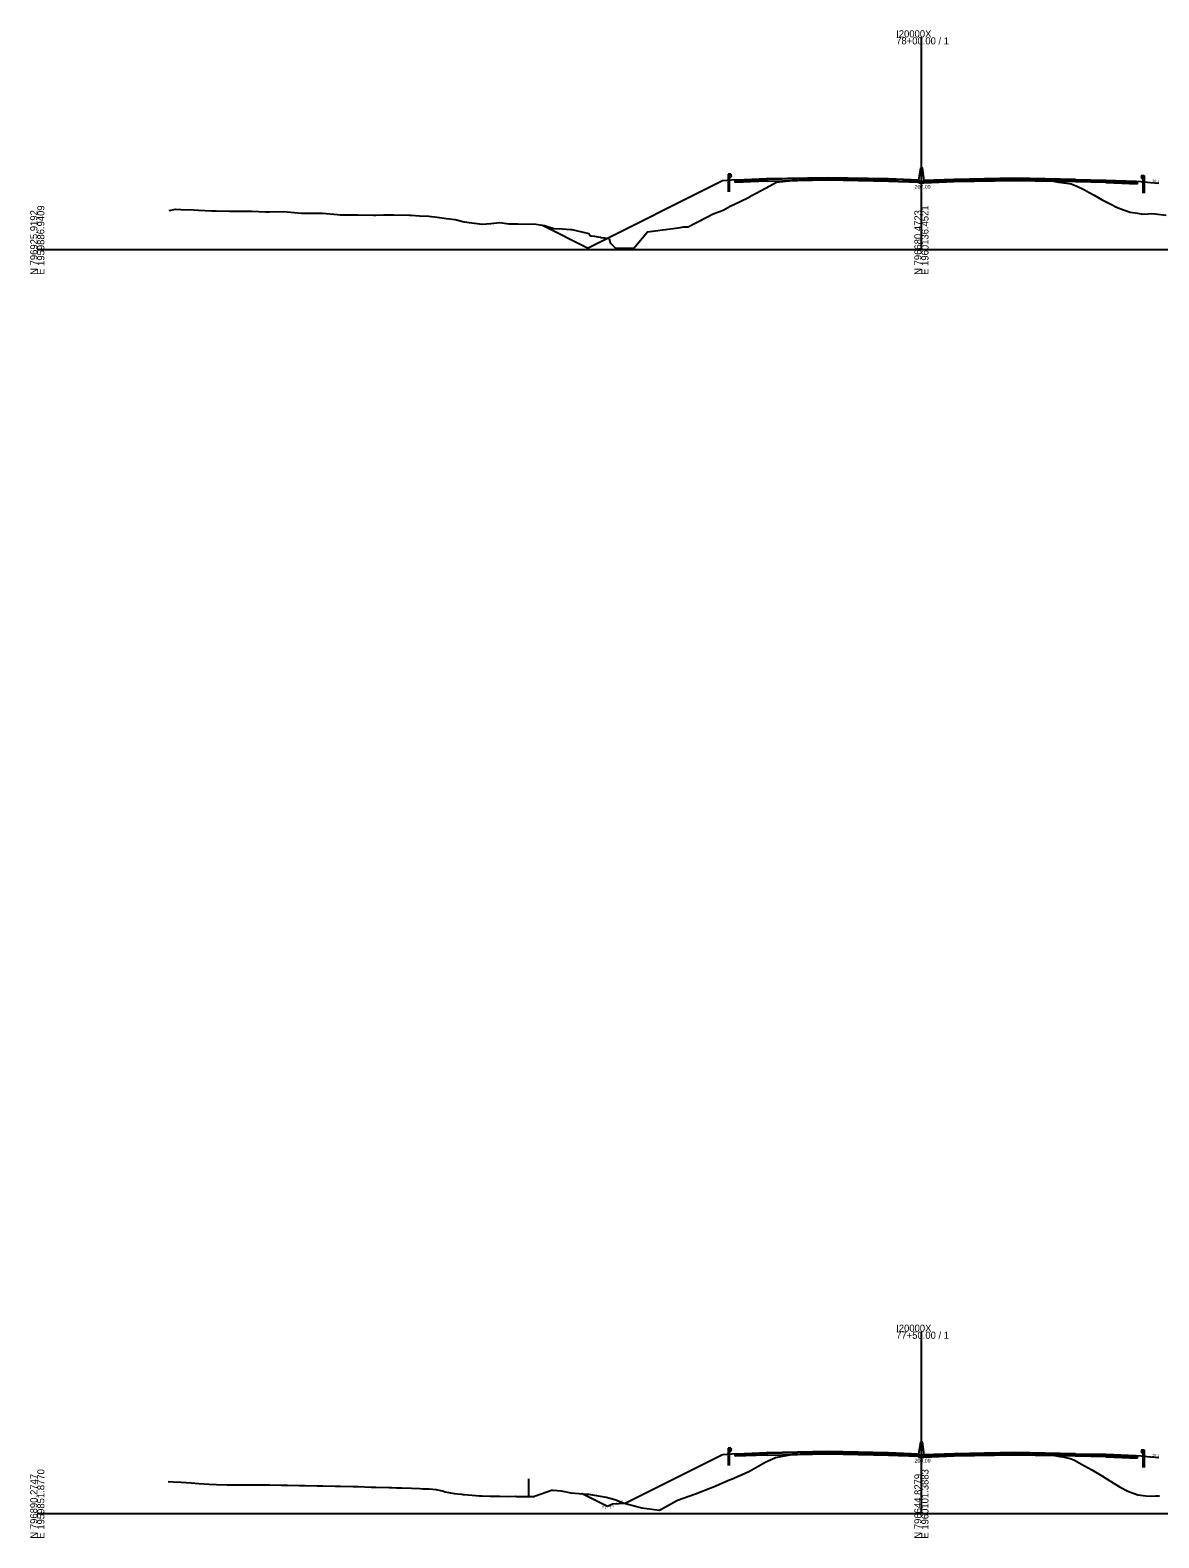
# Model space of a CAD drawing. Extents: x -4026 to 9638, y -10 to 19609.
# Drawn here: x -1003 to -556, y 7490 to 8087 of the extents above; entities that cross this region are included whole.
import ezdxf

# ---------------------------------------------------------------- set-up
doc = ezdxf.new("R2010")
doc.units = 0
for name, color, linetype in [('Default', 7, 'Continuous'), ('RD_EX_Fence_Other', 7, 'Continuous'), ('RD_GPK_XS_Cell', 7, 'Continuous'), ('RD_XS_Base', 7, 'Continuous'), ('RD_XS_ExGround', 7, 'Continuous'), ('RD_XS_GR', 7, 'Continuous'), ('RD_XS_Greenside', 7, 'Continuous'), ('RD_XS_MedBWall', 7, 'Continuous'), ('RD_XS_Pave', 7, 'Continuous'), ('RD_XS_PaveOvlay', 7, 'Continuous'), ('RD_XS_TX_Ditch', 7, 'Continuous'), ('RD_XS_TX_Elev_EX', 7, 'Continuous'), ('RD_XS_TX_Slope', 7, 'Continuous')]:
    doc.layers.add(name, color=color, linetype=linetype)

msp = doc.modelspace()

# ---------------------------------------------------------------- linework, layer by layer
at = {"layer": 'RD_EX_Fence_Other'}
msp.add_line((-805.49, 7513.7), (-805.49, 7506.7), dxfattribs=at)
at = {"layer": 'RD_GPK_XS_Cell'}
for p, q in [((-650, 8000), (-650, 8083.98)), ((-1000, 8000), (-650, 8000)), ((-650, 8000), (-300, 8000)), ((-650, 7500), (-650, 7571.86)), ((-1000, 7500), (-650, 7500)), ((-650, 7500), (-300, 7500))]:
    msp.add_line(p, q, dxfattribs=at)
at = {"layer": 'RD_XS_Base'}
for points in [[(-723.75, 8027.26), (-723.25, 8027.28), (-711.25, 8027.75)], [(-723.75, 8026.59), (-723.75, 8027.26)], [(-711.25, 8027.08), (-723.75, 8026.59)], [(-711.25, 8027.75), (-711, 8027.75)], [(-711.25, 8027.08), (-711.25, 8027.75)], [(-711, 8027.08), (-711.25, 8027.08)], [(-663, 8027.76), (-687, 8028.24), (-711, 8027.75)], [(-711, 8027.75), (-711, 8027.08)], [(-711, 8027.08), (-687, 8027.57), (-663, 8027.09)], [(-651, 8027.29), (-663, 8027.76)], [(-663, 8027.76), (-663, 8027.09)], [(-663, 8027.09), (-651, 8026.62)], [(-651, 8026.62), (-651, 8027.29)], [(-649, 8026.94), (-637, 8027.43)], [(-649, 8026.27), (-649, 8026.94)], [(-637, 8026.76), (-649, 8026.27)], [(-637, 8027.43), (-613, 8027.92), (-589, 8027.43)], [(-637, 8026.76), (-637, 8027.43)], [(-589, 8026.76), (-613, 8027.25), (-637, 8026.76)], [(-589, 8027.43), (-577, 8027.19)], [(-589, 8026.76), (-589, 8027.43)], [(-577, 8026.52), (-589, 8026.76)], [(-577, 8027.19), (-577, 8026.52)], [(-564.5, 8026.7), (-565, 8026.72), (-577, 8027.19)], [(-577, 8026.52), (-564.5, 8026.03)], [(-564.5, 8026.03), (-564.5, 8026.7)], [(-723.75, 7523.23), (-723.25, 7523.25), (-711.25, 7523.72)], [(-723.75, 7522.56), (-723.75, 7523.23)], [(-711.25, 7523.05), (-723.75, 7522.56)], [(-711.25, 7523.72), (-711, 7523.73)], [(-711.25, 7523.05), (-711.25, 7523.72)], [(-711, 7523.06), (-711.25, 7523.05)], [(-663, 7523.73), (-687, 7524.22), (-711, 7523.73)], [(-711, 7523.73), (-711, 7523.06)], [(-711, 7523.06), (-687, 7523.55), (-663, 7523.06)], [(-651, 7523.26), (-663, 7523.73)], [(-663, 7523.73), (-663, 7523.06)], [(-663, 7523.06), (-651, 7522.59)], [(-651, 7522.59), (-651, 7523.26)], [(-649, 7522.76), (-637, 7523.25)], [(-649, 7522.09), (-649, 7522.76)], [(-637, 7522.58), (-649, 7522.09)], [(-637, 7523.25), (-613, 7523.73), (-589, 7523.25)], [(-637, 7522.58), (-637, 7523.25)], [(-589, 7522.58), (-613, 7523.06), (-637, 7522.58)], [(-589, 7523.25), (-577, 7523.01)], [(-589, 7522.58), (-589, 7523.25)], [(-577, 7522.34), (-589, 7522.58)], [(-577, 7523.01), (-577, 7522.34)], [(-564.5, 7522.51), (-565, 7522.53), (-577, 7523.01)], [(-577, 7522.34), (-564.5, 7521.84)], [(-564.5, 7521.84), (-564.5, 7522.51)]]:
    msp.add_lwpolyline(points, dxfattribs=at)
at = {"layer": 'RD_XS_ExGround'}
for points in [[(-947.76, 8015.45), (-945.29, 8015.93), (-943.18, 8015.87), (-938.16, 8015.69), (-936.16, 8015.54), (-931.03, 8015.37), (-929.15, 8015.27), (-923.9, 8015.16), (-922.14, 8015.22), (-916.77, 8015.19), (-915.12, 8015.21), (-909.64, 8014.92), (-908.11, 8014.96), (-902.51, 8015.04), (-901.09, 8014.94), (-898.26, 8014.65), (-895.38, 8014.46), (-894.72, 8014.47), (-894.08, 8014.41), (-891.19, 8014.35), (-888.25, 8014.41), (-887.65, 8014.44), (-887.07, 8014.39), (-881.12, 8013.83), (-880.05, 8013.79), (-873.99, 8013.75), (-873.51, 8013.75), (-873.04, 8013.75), (-866.86, 8013.65), (-866.44, 8013.64), (-866.03, 8013.66), (-862.9, 8013.8), (-859.73, 8013.73), (-859.37, 8013.71), (-859.01, 8013.75), (-852.6, 8013.63), (-852, 8013.62), (-848.76, 8013.42), (-844.98, 8013.23), (-841.69, 8012.88), (-837.97, 8012.32), (-834.62, 8011.85), (-830.96, 8011), (-823.94, 8010.03), (-820.47, 8010.36), (-816.93, 8010.73), (-813.4, 8010.17), (-809.82, 8010.24), (-802.69, 8010.04), (-799.26, 8009.5), (-795.56, 8008.37), (-792.19, 8008.26), (-788.87, 8007.94), (-788.43, 8007.9), (-781.66, 8006.32), (-781.17, 8005.53), (-780.8, 8005.47), (-779.41, 8005.25), (-778.09, 8005.04), (-777.1, 8004.88), (-776.78, 8004.83), (-775.78, 8004.67), (-775.45, 8004.62), (-774.74, 8004.5), (-773.64, 8004.33), (-773.25, 8002.61), (-771.65, 8001.05), (-771.11, 8000.52), (-765.64, 8000.58), (-765.13, 8000.59), (-764.79, 8000.6), (-763.89, 8000.62), (-763.14, 8001.31), (-758.48, 8007.03), (-746.26, 8008.57), (-744.01, 8009.06), (-742.69, 8008.99), (-742.36, 8008.98), (-739.78, 8010.35), (-738.52, 8011.03), (-732.76, 8014.01), (-732.08, 8014.29), (-731.39, 8014.58), (-728.55, 8015.57), (-725.75, 8017.14), (-724.26, 8017.89), (-721.48, 8019.17), (-718.74, 8020.52), (-717.94, 8020.93), (-717.13, 8021.38), (-711.72, 8024.27), (-710, 8025.16), (-707.33, 8026.61), (-702.33, 8027.21), (-701.17, 8027.36), (-695.89, 8027.58), (-691.66, 8027.76), (-681.82, 8027.96), (-680.48, 8027.99), (-679.2, 8027.97), (-669.05, 8027.81), (-657.33, 8027.55), (-651.75, 8027.07), (-651.05, 8027.08), (-650, 8027.09), (-647.77, 8027.1), (-644.4, 8027.32), (-642.43, 8027.46), (-636.64, 8027.58), (-630.82, 8027.71), (-624.59, 8027.84), (-619.17, 8027.95), (-615.91, 8027.87), (-607.64, 8027.65), (-600.03, 8027.27), (-598.85, 8027.22), (-598.43, 8027.15), (-595.78, 8026.74), (-594.48, 8026.52), (-590.66, 8026.03), (-588.79, 8025.29), (-585.48, 8023.59), (-583.59, 8022.58), (-581.66, 8021.56), (-580.05, 8020.67), (-578.46, 8019.69), (-574.53, 8017.68), (-572.98, 8016.86), (-571.45, 8016.21), (-567.4, 8014.83), (-564.44, 8014.36), (-562.37, 8013.95), (-560.27, 8014.18), (-558.84, 8014.27), (-557.42, 8014.21), (-553.14, 8013.61)], [(-948.17, 7512.61), (-946.21, 7512.5), (-943.09, 7512.29), (-939.08, 7512.01), (-936.07, 7511.8), (-931.95, 7511.53), (-929.06, 7511.45), (-924.82, 7511.31), (-922.05, 7511.28), (-917.69, 7511.27), (-915.03, 7511.25), (-910.56, 7511.25), (-908.02, 7511.25), (-903.43, 7511.17), (-901, 7511.14), (-896.3, 7511.07), (-893.99, 7511.05), (-889.17, 7510.94), (-886.98, 7510.88), (-882.04, 7510.78), (-879.96, 7510.75), (-874.91, 7510.64), (-872.95, 7510.57), (-867.78, 7510.42), (-865.94, 7510.38), (-860.65, 7510.23), (-859.78, 7510.22), (-857.87, 7510.15), (-857.18, 7510.13), (-855.66, 7510.06), (-851.86, 7509.92), (-848.6, 7509.8), (-847.42, 7509.76), (-846.91, 7509.74), (-845.64, 7509.68), (-844.89, 7509.66), (-842.1, 7509.49), (-839.26, 7508.71), (-838.56, 7508.55), (-837.88, 7508.37), (-835.03, 7507.86), (-832.13, 7507.59), (-831.49, 7507.51), (-830.87, 7507.46), (-825, 7506.95), (-824.42, 7506.93), (-823.85, 7506.94), (-820.89, 7506.83), (-817.87, 7506.79), (-817.35, 7506.79), (-816.84, 7506.77), (-813.81, 7506.6), (-810.74, 7506.74), (-810.28, 7506.69), (-809.83, 7506.7), (-803.61, 7506.7), (-803.21, 7506.7), (-802.81, 7506.99), (-796.48, 7509.14), (-796.14, 7509.17), (-795.8, 7509.15), (-792.6, 7508.85), (-788.78, 7508.18), (-782.22, 7507.58), (-781.77, 7507.54), (-774.76, 7506.38), (-771.39, 7505.48), (-767.74, 7504.03), (-760.73, 7502.2), (-754.73, 7501.39), (-753.7, 7501.26), (-746.57, 7505.22), (-739.44, 7507.67), (-732.68, 7510.36), (-732.31, 7510.49), (-725.66, 7513.33), (-725.18, 7513.54), (-718.65, 7516.42), (-718.05, 7516.73), (-711.63, 7520.35), (-710.92, 7520.7), (-707.74, 7522.16), (-702.02, 7523.12), (-700.93, 7523.31), (-695.28, 7523.55), (-691.79, 7523.69), (-685.05, 7523.85), (-680.44, 7523.95), (-674.26, 7523.84), (-668.93, 7523.74), (-662.76, 7523.61), (-657.45, 7523.5), (-652.62, 7523.14), (-651.92, 7523.08), (-650, 7523.09), (-648.54, 7523.1), (-647.93, 7523.1), (-646.18, 7523.22), (-642.39, 7523.48), (-640.89, 7523.51), (-630.84, 7523.73), (-623.21, 7523.86), (-619.26, 7523.94), (-614.53, 7523.81), (-607.69, 7523.64), (-600.33, 7523.3), (-598.77, 7523.21), (-597.95, 7523.06), (-595.22, 7522.55), (-594.04, 7522.33), (-591.07, 7521.75), (-589.71, 7521.11), (-587.53, 7519.95), (-585.39, 7518.75), (-584, 7517.95), (-582.58, 7517.17), (-578.37, 7514.73), (-575.45, 7512.86), (-571.36, 7510.33), (-568.32, 7508.76), (-564.35, 7507.32), (-561.19, 7506.88), (-559.25, 7506.76), (-557.33, 7506.9), (-555.71, 7506.97)]]:
    msp.add_lwpolyline(points, dxfattribs=at)
at = {"layer": 'RD_XS_GR'}
for points in [[(-725.98, 8029.85), (-726.48, 8029.85)], [(-726.48, 8029.85), (-726.48, 8027.35)], [(-725.98, 8027.39), (-725.98, 8029.85)], [(-725.49, 8029.85), (-725.98, 8029.85)], [(-725.98, 8029.85), (-725.98, 8028.67)], [(-725.49, 8029.85), (-725.25, 8029.55)], [(-725.49, 8028.67), (-725.49, 8029.85)], [(-725.25, 8029.55), (-725.48, 8029.25)], [(-725.48, 8029.25), (-725.25, 8028.97)], [(-562.76, 8029.29), (-563, 8028.99)], [(-562.76, 8029.29), (-562.27, 8029.29)], [(-562.76, 8028.11), (-562.76, 8029.29)], [(-562.27, 8029.29), (-561.78, 8029.29)], [(-562.27, 8026.83), (-562.27, 8029.29)], [(-562.27, 8029.29), (-562.27, 8028.11)], [(-561.78, 8029.29), (-561.78, 8026.79)], [(-725.98, 8027.39), (-726.48, 8027.35)], [(-726.48, 8027.35), (-725.98, 8027.39)], [(-726.48, 8027.35), (-726.48, 8022.89)], [(-725.98, 8028.67), (-725.49, 8028.67)], [(-725.98, 8022.89), (-725.98, 8027.39)], [(-725.25, 8028.97), (-725.49, 8028.67)], [(-563, 8028.99), (-562.77, 8028.69)], [(-562.77, 8028.69), (-563, 8028.41)], [(-563, 8028.41), (-562.76, 8028.11)], [(-562.27, 8028.11), (-562.76, 8028.11)], [(-562.27, 8022.33), (-562.27, 8026.83)], [(-561.78, 8026.79), (-561.78, 8022.33)], [(-725.98, 7525.83), (-726.48, 7525.83)], [(-726.48, 7525.83), (-726.48, 7523.33)], [(-725.98, 7523.37), (-726.48, 7523.33)], [(-726.48, 7523.33), (-725.98, 7523.37)], [(-726.48, 7523.33), (-726.48, 7518.87)], [(-725.98, 7523.37), (-725.98, 7525.83)], [(-725.49, 7525.83), (-725.98, 7525.83)], [(-725.98, 7525.83), (-725.98, 7524.65)], [(-725.98, 7524.65), (-725.49, 7524.65)], [(-725.98, 7518.87), (-725.98, 7523.37)], [(-725.49, 7525.83), (-725.25, 7525.53)], [(-725.49, 7524.65), (-725.49, 7525.83)], [(-725.25, 7524.95), (-725.49, 7524.65)], [(-725.25, 7525.53), (-725.48, 7525.23)], [(-725.48, 7525.23), (-725.25, 7524.95)], [(-562.76, 7525.11), (-563, 7524.81)], [(-563, 7524.81), (-562.77, 7524.51)], [(-562.77, 7524.51), (-563, 7524.23)], [(-563, 7524.23), (-562.76, 7523.93)], [(-562.76, 7525.11), (-562.27, 7525.11)], [(-562.76, 7523.93), (-562.76, 7525.11)], [(-562.27, 7523.93), (-562.76, 7523.93)], [(-562.27, 7525.11), (-561.78, 7525.11)], [(-562.27, 7522.65), (-562.27, 7525.11)], [(-562.27, 7525.11), (-562.27, 7523.93)], [(-562.27, 7518.15), (-562.27, 7522.65)], [(-561.78, 7525.11), (-561.78, 7522.61)], [(-561.78, 7522.61), (-561.78, 7518.15)]]:
    msp.add_lwpolyline(points, dxfattribs=at)
at = {"layer": 'RD_XS_Greenside'}
for p, q in [((-559.25, 8026.54), (-556, 8026.22)), ((-559.25, 7522.36), (-556, 7522.03)), ((-774.24, 7502.65), (-784.53, 7507.79)), ((-772.24, 7503.65), (-774.24, 7502.65)), ((-767.24, 7503.9), (-772.24, 7503.65))]:
    msp.add_line(p, q, dxfattribs=at)
for points in [[(-725.25, 8027.45), (-728.75, 8027.17), (-781.93, 8000.58)], [(-723.25, 8027.61), (-725.25, 8027.45)], [(-565, 8027.05), (-563, 8026.89)], [(-563, 8026.89), (-561.78, 8026.79)], [(-561.78, 8026.79), (-559.25, 8026.54)], [(-725.25, 7523.42), (-728.75, 7523.14), (-767.24, 7503.9)], [(-723.25, 7523.58), (-725.25, 7523.42)], [(-565, 7522.87), (-563, 7522.71)], [(-563, 7522.71), (-561.78, 7522.61)], [(-561.78, 7522.61), (-559.25, 7522.36)]]:
    msp.add_lwpolyline(points, dxfattribs=at)
at = {"layer": 'RD_XS_MedBWall'}
for points in [[(-651, 8027.61), (-650.25, 8032.28)], [(-650.25, 8032.28), (-649.75, 8032.28), (-649, 8027.27)], [(-651, 8026.27), (-651, 8027.29), (-651, 8027.61)], [(-649, 8026.27), (-651, 8026.27)], [(-649, 8027.27), (-649, 8026.94), (-649, 8026.27)], [(-651, 7523.59), (-650.25, 7528.26)], [(-650.25, 7528.26), (-649.75, 7528.26), (-649, 7523.09)], [(-651, 7522.09), (-651, 7523.26), (-651, 7523.59)], [(-649, 7522.09), (-651, 7522.09)], [(-649, 7523.09), (-649, 7522.76), (-649, 7522.09)]]:
    msp.add_lwpolyline(points, dxfattribs=at)
at = {"layer": 'RD_XS_Pave'}
for points in [[(-723.25, 8027.44), (-711.25, 8027.92)], [(-711.25, 8027.75), (-723.25, 8027.28)], [(-723.25, 8027.28), (-723.25, 8027.44)], [(-711.25, 8027.92), (-711, 8027.92)], [(-711.25, 8027.75), (-711.25, 8027.92)], [(-711, 8027.75), (-711.25, 8027.75)], [(-711, 8027.92), (-687, 8028.41), (-663, 8027.93)], [(-663, 8027.76), (-687, 8028.24), (-711, 8027.75)], [(-711, 8027.92), (-711, 8027.75)], [(-663, 8027.93), (-663, 8027.76)], [(-663, 8027.93), (-651, 8027.46)], [(-651, 8027.29), (-663, 8027.76)], [(-651, 8027.46), (-651, 8027.29)], [(-637, 8027.6), (-649, 8027.11)], [(-649, 8026.94), (-637, 8027.43)], [(-649, 8027.11), (-649, 8026.94)], [(-589, 8027.6), (-613, 8028.08), (-637, 8027.6)], [(-637, 8027.43), (-613, 8027.92), (-589, 8027.43)], [(-637, 8027.6), (-637, 8027.43)], [(-589, 8027.6), (-577, 8027.36)], [(-589, 8027.43), (-589, 8027.6)], [(-577, 8027.19), (-589, 8027.43)], [(-577, 8027.36), (-577, 8027.19)], [(-565, 8026.88), (-577, 8027.36)], [(-577, 8027.19), (-565, 8026.72)], [(-565, 8026.72), (-565, 8026.88)], [(-723.25, 7523.42), (-711.25, 7523.89)], [(-711.25, 7523.72), (-723.25, 7523.25)], [(-723.25, 7523.25), (-723.25, 7523.42)], [(-711.25, 7523.89), (-711, 7523.9)], [(-711.25, 7523.72), (-711.25, 7523.89)], [(-711, 7523.73), (-711.25, 7523.72)], [(-711, 7523.9), (-687, 7524.38), (-663, 7523.9)], [(-663, 7523.73), (-687, 7524.22), (-711, 7523.73)], [(-711, 7523.9), (-711, 7523.73)], [(-663, 7523.9), (-663, 7523.73)], [(-663, 7523.9), (-651, 7523.43)], [(-651, 7523.26), (-663, 7523.73)], [(-651, 7523.43), (-651, 7523.26)], [(-637, 7523.42), (-649, 7522.93)], [(-649, 7522.76), (-637, 7523.25)], [(-649, 7522.93), (-649, 7522.76)], [(-589, 7523.42), (-613, 7523.9), (-637, 7523.42)], [(-637, 7523.25), (-613, 7523.73), (-589, 7523.25)], [(-637, 7523.42), (-637, 7523.25)], [(-589, 7523.42), (-577, 7523.18)], [(-589, 7523.25), (-589, 7523.42)], [(-577, 7523.01), (-589, 7523.25)], [(-577, 7523.18), (-577, 7523.01)], [(-565, 7522.7), (-577, 7523.18)], [(-577, 7523.01), (-565, 7522.53)], [(-565, 7522.53), (-565, 7522.7)]]:
    msp.add_lwpolyline(points, dxfattribs=at)
at = {"layer": 'RD_XS_PaveOvlay'}
for points in [[(-723.25, 8027.61), (-711.25, 8028.09)], [(-711.25, 8027.92), (-723.25, 8027.44)], [(-723.25, 8027.44), (-723.25, 8027.61)], [(-711.25, 8028.09), (-711.25, 8027.92)], [(-711, 8028.09), (-711.25, 8028.09)], [(-711.25, 8027.92), (-711, 8027.92)], [(-711, 8028.09), (-687, 8028.57), (-663, 8028.09)], [(-663, 8027.93), (-687, 8028.41), (-711, 8027.92)], [(-711, 8027.92), (-711, 8028.09)], [(-663, 8028.09), (-663, 8027.93)], [(-663, 8028.09), (-651, 8027.61)], [(-651, 8027.46), (-663, 8027.93)], [(-651, 8027.61), (-651, 8027.46)], [(-637, 8027.77), (-649, 8027.27)], [(-649, 8027.11), (-637, 8027.6)], [(-649, 8027.27), (-649, 8027.11)], [(-589, 8027.77), (-613, 8028.25), (-637, 8027.77)], [(-637, 8027.6), (-613, 8028.08), (-589, 8027.6)], [(-637, 8027.77), (-637, 8027.6)], [(-589, 8027.6), (-589, 8027.77)], [(-589, 8027.77), (-577, 8027.53)], [(-577, 8027.36), (-589, 8027.6)], [(-577, 8027.53), (-577, 8027.36)], [(-577, 8027.53), (-565, 8027.05)], [(-565, 8026.88), (-577, 8027.36)], [(-565, 8027.05), (-565, 8026.88)], [(-723.25, 7523.58), (-711.25, 7524.06)], [(-711.25, 7523.89), (-723.25, 7523.42)], [(-723.25, 7523.42), (-723.25, 7523.58)], [(-711, 7524.07), (-711.25, 7524.06)], [(-711.25, 7524.06), (-711.25, 7523.89)], [(-711.25, 7523.89), (-711, 7523.9)], [(-711, 7524.07), (-687, 7524.55), (-663, 7524.07)], [(-663, 7523.9), (-687, 7524.38), (-711, 7523.9)], [(-711, 7523.9), (-711, 7524.07)], [(-663, 7524.07), (-663, 7523.9)], [(-663, 7524.07), (-651, 7523.59)], [(-651, 7523.43), (-663, 7523.9)], [(-651, 7523.59), (-651, 7523.43)], [(-637, 7523.59), (-649, 7523.09)], [(-649, 7522.93), (-637, 7523.42)], [(-649, 7523.09), (-649, 7522.93)], [(-589, 7523.59), (-613, 7524.07), (-637, 7523.59)], [(-637, 7523.42), (-613, 7523.9), (-589, 7523.42)], [(-637, 7523.59), (-637, 7523.42)], [(-589, 7523.42), (-589, 7523.59)], [(-589, 7523.59), (-577, 7523.35)], [(-577, 7523.18), (-589, 7523.42)], [(-577, 7523.35), (-577, 7523.18)], [(-577, 7523.35), (-565, 7522.87)], [(-565, 7522.7), (-577, 7523.18)], [(-565, 7522.87), (-565, 7522.7)]]:
    msp.add_lwpolyline(points, dxfattribs=at)
at = {"layer": 'RD_XS_TX_Ditch'}
msp.add_line((-800, 8009.62), (-781.93, 8000.58), dxfattribs=at)

# ---------------------------------------------------------------- texts
at = {"layer": 'Default'}
for p in [(-1000, 8000), (-1000, 7500)]:
    msp.add_text('-', height=0.0001, dxfattribs=at).set_placement(p)
at = {"layer": 'RD_GPK_XS_Cell'}
for s, p in [('78+00.00 / 1', (-660, 8081.18)), ('I20000X', (-660, 8083.98)), ('77+50.00 / 1', (-660, 7569.06)), ('I20000X', (-660, 7571.86))]:
    msp.add_text(s, height=2.8, dxfattribs=at).set_placement(p)
for s, p in [('E 1959886.9409', (-997.2, 7990)), ('E 1960136.4521', (-647.2, 7990)), ('N 796925.9192', (-1000, 7990)), ('N 796680.4723', (-650, 7990)), ('E 1959851.8770', (-997.2, 7490)), ('E 1960101.3883', (-647.2, 7490)), ('N 796890.2747', (-1000, 7490)), ('N 796644.8279', (-650, 7490))]:
    msp.add_text(s, height=2.8, rotation=90, dxfattribs=at).set_placement(p)
at = {"layer": 'RD_XS_TX_Elev_EX'}
for s, p in [('207.09', (-652.69, 8024.09)), ('209.09', (-652.69, 7520.09))]:
    msp.add_text(s, height=1.5, dxfattribs=at).set_placement(p)
at = {"layer": 'RD_XS_TX_Slope'}
for s, rotation, p in [('10:1', 354.28941, (-558.63, 8026.78)), ('10:1', 354.28941, (-558.63, 7522.6)), ('20:1', 2.86241, (-770.8, 7503.97)), ('2:1', 333.43495, (-776.59, 7502.54)), ('2:1', 26.56505, (-773.17, 7501.82))]:
    msp.add_text(s, height=1, rotation=rotation, dxfattribs=at).set_placement(p)

doc.saveas('drawing.dxf')
